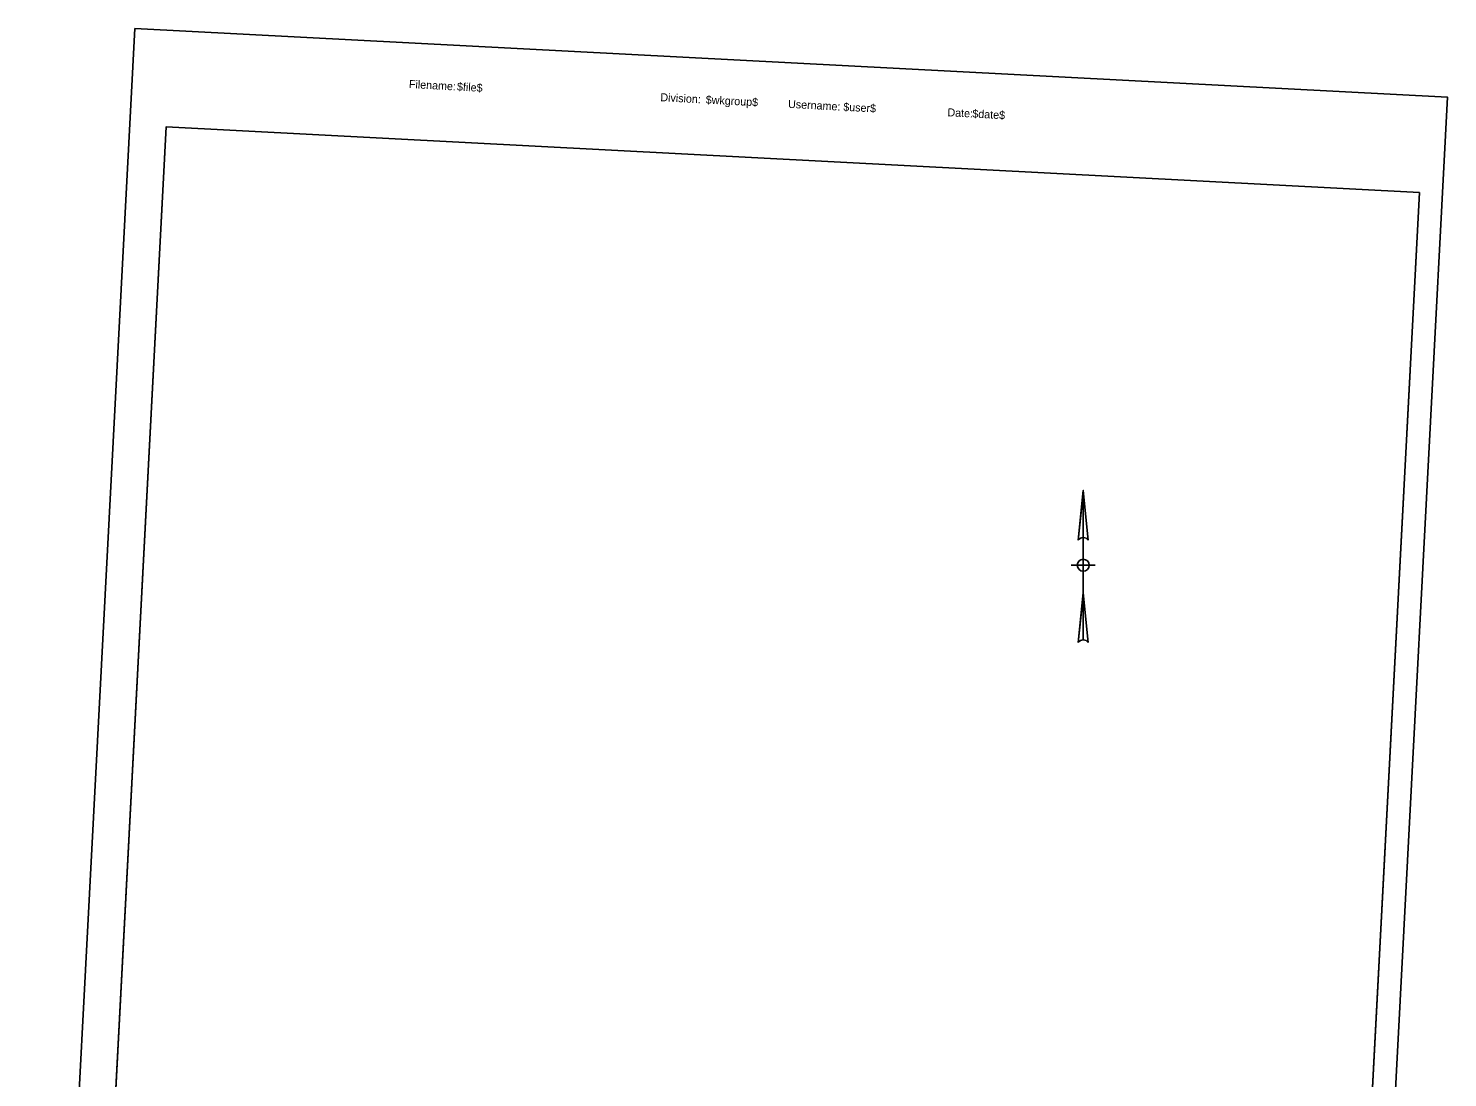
# Model space of a CAD drawing. Extents: x 1764065 to 1764658, y 480559 to 481437.
# Drawn here: x 1764065 to 1764658, y 480998 to 481437 of the extents above; entities that cross this region are included whole.
import ezdxf

# ---------------------------------------------------------------- set-up
doc = ezdxf.new("R2010")
doc.units = 0
for name, color, linetype in [('CLIPS', 7, 'Continuous'), ('D_Drainage_Ditch_Line', 7, 'Continuous'), ('H_V CONTROLS', 7, 'Continuous'), ('PLOT BOUNDARY', 7, 'Continuous')]:
    doc.layers.add(name, color=color, linetype=linetype)

msp = doc.modelspace()

# ---------------------------------------------------------------- linework, layer by layer
at = {"layer": 'CLIPS'}
msp.add_lwpolyline([(1764646.6, 481368.14), (1764607.35, 480619.16), (1764083.07, 480646.64), (1764122.32, 481395.61)], close=True, dxfattribs=at)
at = {"layer": 'D_Drainage_Ditch_Line'}
for p, q in [((1764503.89, 481222.73), (1764505.97, 481243.57)), ((1764505.97, 481243.57), (1764505.97, 481181.07)), ((1764505.97, 481243.57), (1764508.06, 481222.73)), ((1764500.97, 481212.32), (1764510.97, 481212.32)), ((1764503.89, 481179.95), (1764505.97, 481200.78)), ((1764505.97, 481200.78), (1764508.06, 481179.95))]:
    msp.add_line(p, q, dxfattribs=at)
for points in [[(1764508.06, 481222.73), (1764505.97, 481243.57), (1764504.93, 481233.15), (1764503.89, 481222.73)], [(1764508.06, 481179.95), (1764505.97, 481200.78), (1764504.93, 481190.37), (1764503.89, 481179.95)]]:
    msp.add_lwpolyline(points, dxfattribs=at)
msp.add_circle((1764505.97, 481212.32), 2.5, dxfattribs=at)
for centre in [(1764505.97, 481221.35), (1764505.97, 481221.35), (1764505.97, 481178.57), (1764505.97, 481178.57)]:
    msp.add_arc(centre, 2.5, 33.55731, 146.44269, dxfattribs=at)
at = {"layer": 'H_V CONTROLS'}
msp.add_lwpolyline([(1764646.6, 481368.14), (1764604.73, 480569.23), (1764080.45, 480596.71), (1764122.32, 481395.61)], close=True, dxfattribs=at)
at = {"layer": 'PLOT BOUNDARY'}
msp.add_lwpolyline([(1764109.17, 481436.82), (1764064.68, 480587.99), (1764613.93, 480559.2), (1764658.41, 481408.04)], close=True, dxfattribs=at)

# ---------------------------------------------------------------- texts
at = {"layer": 'H_V CONTROLS'}
for s, p in [('Filename:', (1764223.81, 481411.9)), ('$file$', (1764243.91, 481410.84)), ('Division:', (1764329, 481406.39)), ('$wkgroup$', (1764347.99, 481405.39)), ('Username:', (1764382.43, 481403.59)), ('$user$', (1764405.52, 481402.38)), ('Date:', (1764449.09, 481400.09)), ('$date$', (1764459.52, 481399.55))]:
    msp.add_text(s, height=3.348, rotation=357, dxfattribs=at).set_placement(p)

doc.saveas('drawing.dxf')
